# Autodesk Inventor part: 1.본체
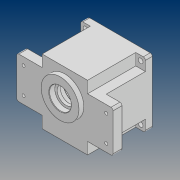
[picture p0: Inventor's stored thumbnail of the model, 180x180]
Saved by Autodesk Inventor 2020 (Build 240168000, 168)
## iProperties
Created: 2020-07
Part Number: 1.본체
Material: 일반
Document SubType Name: Modeling
Designer: PC312-
Density: 1 g/cm^3
Appearance: 기본값
Author: PC312-
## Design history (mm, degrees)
sketch "스케치1"
  geometry: L1 (47, 47)-(-47, 47); L2 (-47, 47)-(-47, -47); L3 (-47, -47)-(47, -47); L4 (47, -47)-(47, 47); L5 (47, 47)-(-47, -47); L6 (-47, 47)-(47, -47); 1 further point
  constraints: 12 end point, 2 midpoint, 2 parallel, 1 horizontal, 1 perpendicular
  dimensions: "d0" = 94 distance of L1.start L1.end; "d1" = 94 distance of L3.end L1.start
extrude "돌출1" new body sketch "스케치1" distance "d2" = 10; taper "d3" = 0 deg
sketch "스케치2"
  geometry: L1 (33, 47)-(-33, 47); L2 (-33, 47)-(-33, -47); L3 (-33, -47)-(33, -47); L4 (33, -47)-(33, 47); L5 (33, 47)-(-33, -47); L6 (-33, 47)-(33, -47); L7 (47, 47)-(-47, 47) reference; L8 (47, 30)-(-47, 30); L9 (-47, 30)-(-47, -30); L10 (-47, -30)-(47, -30); L11 (47, -30)-(47, 30); L12 (47, 30)-(-47, -30); L13 (-47, 30)-(47, -30); L14 (47, -47)-(47, 47) reference; 5 further points
  constraints: 24 end point, 4 midpoint, 4 parallel, 2 collinear, 2 horizontal, 2 perpendicular
  dimensions: "d4" = 66 distance of L1.start L1.end; "d5" = 60 distance of L10.end L8.start
extrude "돌출2" join sketch "스케치2" distance "d6" = 57; taper "d7" = 0 deg
sketch "스케치3"
  geometry: L1 (70, 30)-(-70, 30); L2 (-70, 30)-(-70, -30); L3 (-70, -30)-(70, -30); L4 (70, -30)-(70, 30); L5 (70, 30)-(-70, -30); L6 (-70, 30)-(70, -30); L7 (33, 47)-(-33, 47) reference; L8 (-33, 47)-(-33, 30) reference; L9 (33, 30)-(33, 47) reference; L10 (33, -47)-(33, -30) reference; L11 (-33, -47)-(33, -47) reference; L12 (-33, -30)-(-33, -47) reference; 1 further point
  constraints: 12 end point, 2 midpoint, 2 parallel, 1 horizontal, 1 perpendicular
  dimensions: "d8" = 60 distance of L3.end L1.start; "d9" = 140 distance of L1.start L1.end
extrude "돌출3" join sketch "스케치3" distance "d10" = 13; taper "d11" = 0 deg
sketch "스케치4"
  geometry: C1 r 27.5 at (0, 11); 1 further point
  constraints: 1 centre point, 1 vertical alignment
  dimensions: "d12" = 11 distance of point (0, 0) C1.centre; "d13" = 55 diameter of C1
extrude "돌출4" join sketch "스케치4" distance "d14" = 7; taper "d15" = 0 deg
sketch "스케치5"
  geometry: C1 r 43 at (0, 0); 1 further point
  constraints: 1 centre point, 1 coincident
  dimensions: "d16" = 86 diameter of C1
extrude "돌출5" cut sketch "스케치5" distance "d17" = 9; taper "d18" = 0 deg
sketch "스케치10"
  geometry: C1 r 40 at (0, 0); 1 further point
  constraints: 1 centre point, 1 coincident
  dimensions: "d35" = 80 diameter of C1
extrude "돌출8" cut sketch "스케치10" distance "d36" = 71; taper "d37" = 0 deg
sketch "스케치11"
  geometry: A1 r 21 centre (0, 11) between (8.978, -7.984) and (-8.978, -7.984); A2 r 15 centre (0, -20) between (-8.978, -7.984) and (8.978, -7.984); 1 further point
  constraints: 4 point on circle, 2 centre point, 2 vertical alignment
  dimensions: "d38" = 42 diameter of A1; "d39" = 30 diameter of A2; "d40" = 11 distance of point (0, 0) A1.centre; "d41" = 20 distance of point (0, 0) A2.centre
extrude "돌출9" join sketch "스케치11" distance "d42" = 7; taper "d43" = 0 deg
sketch "스케치12"
  geometry: L1 (11, 96.919)-(11, -20.905); L2 (38.5, 87)-(-16.5, 87) reference; L3 (27, 87)-(27, 78.7); L4 (27, 78.7)-(23.5, 78.7); L5 (23.5, 78.7)-(23.5, 74); L6 (23.5, 74)-(28.5, 74); L7 (28.5, 74)-(28.5, 64); L8 (-7.984, 64)-(32, 64) reference; L9 (27, 87)-(11, 87); L10 (28.5, 64)-(11, 64); L11 (11, 87)-(11, 64); 2 further points
  constraints: 18 end point, 4 point on line, 4 vertical, 2 horizontal, 1 midpoint
  dimensions: "d44" = 11 distance from line of point (0, 0) L1; "d45" = 8.3 distance of L3.start L3.end; "d46" = 10 distance of L6.end L7.end; "d47" = 25 diameter of L5 L1; "d48" = 32 diameter of L3 L1; "d49" = 35 diameter of L7 L1
revolve "회전1" sketch "스케치12" stored, may be unused: angle "d50" = 90 deg
sketch "스케치13"
  geometry: L1 (-20, 101.594)-(-20, -10.441); L2 (-35, 64)-(-7.984, 64) reference; L3 (-9, 64)-(-9, 71); L4 (-9, 71)-(-10.5, 71); L5 (-10.5, 71)-(-10.5, 74); L6 (-10.5, 74)-(-20, 74); L7 (-20, 74)-(-20, 64); L8 (-9, 64)-(-20, 64); 1 further point
  constraints: 14 end point, 4 point on line, 3 horizontal, 3 vertical
  dimensions: "d51" = 20 distance from line of point (0, 0) L1; "d52" = 22 diameter of L3 L1; "d53" = 19 diameter of L5 L1; "d54" = 7 distance of L3.start L3.end; "d55" = 3 distance of L4.end L5.end
revolve "회전2" sketch "스케치13" stored, may be unused: angle "d56" = 90 deg
sketch "스케치14"
  geometry: A1 r 36 centre (0, 0) between (-36, 0) and (-35.772, 4.045); A2 r 4 centre (-36, 0) between (-36.19, -3.995) and (-36.19, 3.995); A3 r 3 centre (-36.333, -6.992) between (-35.772, -4.045) and (-39.279, -7.559); A4 r 40 centre (0, 0) between (-39.279, 7.559) and (-39.279, -7.559) reference; A5 r 3 centre (-36.333, 6.992) between (-39.279, 7.559) and (-35.772, 4.045); 1 further point
  constraints: 13 point on circle, 4 centre point, 4 tangent, 1 coincident, 1 horizontal alignment
  dimensions: "d57" = 72 diameter of A1; "d58" = 8 diameter of A2; "d59" = 6 diameter of A3; "d60" = 6 diameter of A5
extrude "돌출10" join sketch "스케치14" distance "d61" = 62; taper "d62" = 0 deg
sketch "스케치15"
  geometry: A1 r 4 centre (-36, 0) between (-36.19, -3.995) and (-36.19, 3.995) reference; 2 further points
  constraints: 1 coincident
hole "구멍1" sketch "스케치15" at (-36, 0) diameter "d63" = 3.242; stored, may be unused: countersink angle "d67" = 90 deg, drill point angle "d69" = 118 deg; dims "d64" = 7, "d65" = 4, "d66" = 2, "d68" = 9
fillet "모깎기1" dims "d70" = 3
sketch "스케치16"
  geometry: L1 (33, -47)-(44, -47) reference; L2 (47, -44)-(47, -30) reference; 2 further points
  dimensions: "d71" = 7 distance from line of L1 point (40, -40); "d72" = 7 distance from line of L2 point (40, -40)
hole "구멍2" sketch "스케치16" at (40, -40) diameter "d73" = 7; stored, may be unused: countersink angle "d77" = 90 deg, drill point angle "d79" = 118 deg; dims "d74" = 7, "d75" = 4, "d76" = 2, "d78" = 9
fillet "모깎기2" dims "d86" = 3
sketch "스케치18"
  geometry: L1 (-67, 30)-(-47, 30) reference; L2 (-70, -27)-(-70, 27) reference; 2 further points
  dimensions: "d87" = 11 distance from line of L1 point (-60, 19); "d88" = 10 distance from line of L2 point (-60, 19)
hole "구멍3" sketch "스케치18" at (-60, 19) diameter "d89" = 4.5; stored, may be unused: countersink angle "d93" = 90 deg, drill point angle "d95" = 118 deg; dims "d90" = 7, "d91" = 10, "d92" = 5, "d94" = 9
chamfer "모따기1" distance "d102" = 0.8; stored, may be unused: second distance "d103" = 2, angle "d104" = 30 deg
chamfer "모따기2" distance "d105" = 1; stored, may be unused: second distance "d106" = 2, angle "d107" = 30 deg
fillet "모깎기3" dims "d108" = 3
node "솔리드1"
mirror "미러1"
pattern_linear "직사각형 패턴1" dims "d82" = 80, "d85" = 80
pattern_linear "직사각형 패턴2" dims "d98" = 38, "d101" = 120
feature "A9D066F2-1C7D-4E18-AEED-F7BC21143FA4" dims "d73" = 7, "d74" = 7, "d75" = 4, "d76" = 2, "d77" = 90 deg, "d78" = 9, "d79" = 118 deg
